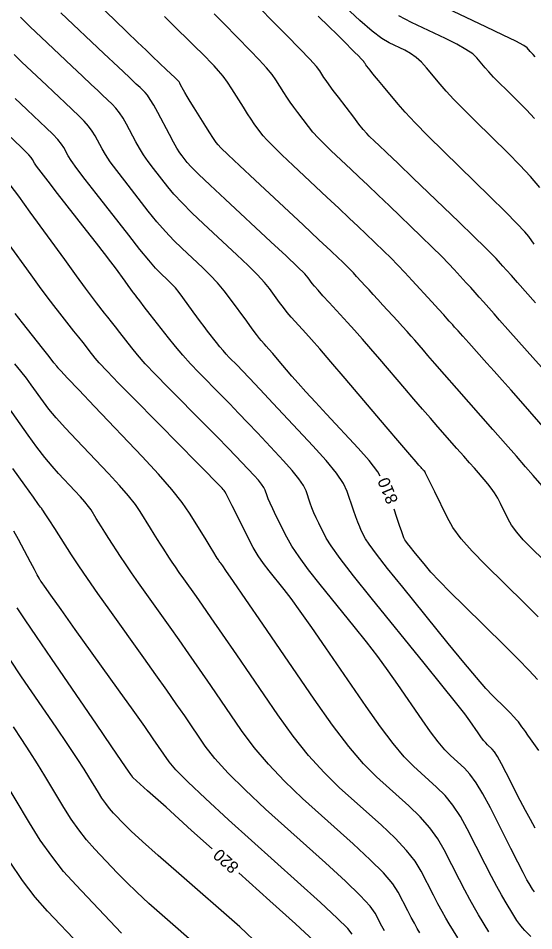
# Model space of a CAD drawing. Extents: x 2082232 to 2083549, y 592624 to 593832.
# Drawn here: x 2082349.4 to 2082379.6, y 593225.4 to 593278.8 of the extents above; entities that cross this region are included whole.
import ezdxf

# ---------------------------------------------------------------- set-up
doc = ezdxf.new("R2010")
doc.units = 0
doc.layers.add('DT_X_Contour_Major', color=7, linetype='Continuous')
doc.layers.add('DT_X_Contour_Minor', color=7, linetype='Continuous')

msp = doc.modelspace()

# ---------------------------------------------------------------- linework, layer by layer
at = {"layer": 'DT_X_Contour_Major'}
for points in [[(2082379.667, 593276.547), (2082379.545, 593276.672), (2082379.447, 593276.777), (2082379.372, 593276.863), (2082379.203, 593277.067), (2082379.004, 593277.202), (2082378.536, 593277.452), (2082377.798, 593277.817), (2082376.791, 593278.299), (2082373.744, 593279.736)], [(2082381.949, 593256.269), (2082379.537, 593258.954), (2082378.716, 593259.869), (2082378.063, 593260.599), (2082377.578, 593261.144), (2082377.26, 593261.504), (2082376.637, 593262.218), (2082376.399, 593262.488), (2082376.154, 593262.764), (2082375.901, 593263.046), (2082375.639, 593263.333), (2082374.932, 593264.106), (2082374.613, 593264.444), (2082374.185, 593264.877), (2082373.65, 593265.406), (2082373.006, 593266.03), (2082371.146, 593267.821), (2082370.481, 593268.459), (2082369.883, 593269.029), (2082369.353, 593269.533), (2082368.888, 593269.969), (2082367.739, 593271.043), (2082367.333, 593271.434), (2082366.975, 593271.802), (2082366.665, 593272.147), (2082366.404, 593272.469), (2082365.773, 593273.297), (2082365.545, 593273.603), (2082365.332, 593273.9), (2082365.136, 593274.188), (2082364.956, 593274.467), (2082364.496, 593275.199), (2082364.273, 593275.512), (2082363.949, 593275.903), (2082363.524, 593276.372), (2082362.999, 593276.919), (2082361.461, 593278.479), (2082360.894, 593279.052)], [(2082370.608, 593252.013), (2082370.455, 593252.266), (2082369.95, 593252.938), (2082369.316, 593253.658), (2082367.455, 593255.645), (2082366.805, 593256.343), (2082366.252, 593256.947), (2082365.794, 593257.456), (2082365.433, 593257.871), (2082364.597, 593258.851), (2082364.314, 593259.182), (2082364.092, 593259.441), (2082363.93, 593259.626), (2082363.829, 593259.739), (2082363.641, 593259.943), (2082363.535, 593260.071), (2082363.358, 593260.302), (2082363.11, 593260.636), (2082362.791, 593261.073), (2082361.845, 593262.374), (2082361.477, 593262.855), (2082361.082, 593263.321), (2082360.661, 593263.772), (2082360.214, 593264.208), (2082358.984, 593265.35), (2082358.516, 593265.808), (2082358.035, 593266.323), (2082357.539, 593266.895), (2082357.03, 593267.525), (2082355.654, 593269.282), (2082355.183, 593269.894), (2082354.805, 593270.411), (2082354.518, 593270.834), (2082354.323, 593271.163), (2082353.924, 593271.914), (2082353.753, 593272.198), (2082353.541, 593272.487), (2082353.286, 593272.78), (2082352.989, 593273.078), (2082352.141, 593273.878), (2082351.812, 593274.188), (2082351.461, 593274.519), (2082351.09, 593274.869), (2082349.62, 593276.257), (2082349.186, 593276.677)], [(2082376.964, 593225.355), (2082376.352, 593226.359), (2082376.11, 593226.77), (2082375.843, 593227.25), (2082375.551, 593227.798), (2082375.233, 593228.415), (2082374.351, 593230.151), (2082373.974, 593230.801), (2082373.502, 593231.446), (2082372.936, 593232.088), (2082372.277, 593232.725), (2082370.391, 593234.421), (2082369.632, 593235.183), (2082368.768, 593236.196), (2082367.8, 593237.46), (2082366.727, 593238.977), (2082363.727, 593243.355), (2082362.737, 593244.8), (2082362.017, 593245.85), (2082361.567, 593246.505), (2082361.387, 593246.766), (2082361.266, 593246.935), (2082361.223, 593246.995), (2082361.187, 593247.047), (2082361.156, 593247.093), (2082361.13, 593247.131), (2082361.07, 593247.225), (2082361.008, 593247.324), (2082360.868, 593247.551), (2082360.648, 593247.908), (2082360.349, 593248.392), (2082359.448, 593249.856), (2082359.022, 593250.474), (2082358.418, 593251.23), (2082357.637, 593252.125), (2082356.678, 593253.158), (2082353.885, 593256.098), (2082352.968, 593257.064), (2082352.313, 593257.755), (2082351.918, 593258.171), (2082351.784, 593258.314), (2082351.774, 593258.327), (2082351.77, 593258.332), (2082351.766, 593258.338), (2082351.761, 593258.343), (2082351.756, 593258.349), (2082351.741, 593258.366), (2082351.681, 593258.441), (2082351.512, 593258.654), (2082351.234, 593259.006), (2082350.847, 593259.495), (2082349.671, 593260.984), (2082349.249, 593261.522)], [(2082379.795, 593240.126), (2082379.318, 593240.654), (2082378.677, 593241.319), (2082377.872, 593242.12), (2082375.509, 593244.437), (2082374.702, 593245.235), (2082374.055, 593245.892), (2082373.569, 593246.409), (2082373.242, 593246.784), (2082372.583, 593247.596), (2082372.364, 593247.868), (2082372.201, 593248.076), (2082372.094, 593248.218), (2082372.044, 593248.296), (2082371.983, 593248.418), (2082371.94, 593248.526), (2082371.857, 593248.761), (2082371.734, 593249.121), (2082371.57, 593249.607), (2082371.411, 593250.081)], [(2082360.761, 593230.223), (2082359.568, 593231.297), (2082358.067, 593232.647), (2082356.993, 593233.614), (2082356.347, 593234.196), (2082356.128, 593234.396), (2082356.115, 593234.415), (2082356.108, 593234.425), (2082356.097, 593234.441), (2082356.082, 593234.462), (2082356.063, 593234.488), (2082356.008, 593234.566), (2082355.866, 593234.771), (2082355.484, 593235.33), (2082354.86, 593236.241), (2082353.995, 593237.505), (2082351.367, 593241.346), (2082350.488, 593242.635), (2082349.821, 593243.622), (2082349.366, 593244.307)], [(2082366.725, 593224.847), (2082365.644, 593225.828), (2082364.14, 593227.184), (2082362.323, 593228.819)]]:
    msp.add_lwpolyline(points, dxfattribs=at)
at = {"layer": 'DT_X_Contour_Minor'}
for points in [[(2082380.597, 593250.854), (2082379.553, 593252.06), (2082379.112, 593252.568), (2082378.571, 593253.186), (2082377.931, 593253.915), (2082377.191, 593254.755), (2082375.085, 593257.143), (2082374.37, 593257.955), (2082373.806, 593258.597), (2082373.392, 593259.072), (2082373.127, 593259.378), (2082372.623, 593259.97), (2082372.418, 593260.207), (2082372.181, 593260.475), (2082371.911, 593260.773), (2082371.61, 593261.102), (2082370.763, 593262.021), (2082370.461, 593262.35), (2082370.189, 593262.645), (2082369.948, 593262.907), (2082369.738, 593263.137), (2082369.219, 593263.704), (2082369.036, 593263.902), (2082368.878, 593264.071), (2082368.744, 593264.209), (2082368.634, 593264.318), (2082368.373, 593264.569), (2082368.157, 593264.774), (2082367.703, 593265.199), (2082367.012, 593265.846), (2082366.084, 593266.714), (2082363.291, 593269.323), (2082362.369, 593270.186), (2082361.698, 593270.818), (2082361.279, 593271.22), (2082361.111, 593271.392), (2082360.997, 593271.541), (2082360.928, 593271.641), (2082360.805, 593271.829), (2082360.629, 593272.105), (2082360.399, 593272.469), (2082359.717, 593273.556), (2082359.485, 593273.927), (2082359.303, 593274.224), (2082359.169, 593274.448), (2082359.085, 593274.598), (2082358.925, 593274.899), (2082358.871, 593274.999), (2082358.829, 593275.074), (2082358.799, 593275.123), (2082358.781, 593275.147), (2082358.749, 593275.178), (2082358.7, 593275.224), (2082358.576, 593275.341), (2082358.103, 593275.788), (2082357.274, 593276.571), (2082356.901, 593276.925), (2082356.406, 593277.4), (2082355.789, 593277.995), (2082355.049, 593278.712), (2082352.912, 593280.783)], [(2082379.678, 593262.146), (2082378.632, 593263.344), (2082378.276, 593263.751), (2082377.994, 593264.073), (2082377.785, 593264.309), (2082377.649, 593264.46), (2082377.386, 593264.748), (2082377.174, 593264.963), (2082376.738, 593265.391), (2082376.078, 593266.031), (2082375.192, 593266.885), (2082372.532, 593269.447), (2082371.643, 593270.301), (2082370.974, 593270.945), (2082370.523, 593271.376), (2082370.291, 593271.597), (2082369.964, 593271.902), (2082369.814, 593272.057), (2082369.613, 593272.293), (2082369.358, 593272.61), (2082369.051, 593273.007), (2082368.162, 593274.175), (2082367.858, 593274.576), (2082367.616, 593274.905), (2082367.433, 593275.16), (2082367.311, 593275.343), (2082367.067, 593275.732), (2082366.876, 593275.972), (2082366.488, 593276.399), (2082365.902, 593277.014), (2082365.118, 593277.816), (2082362.764, 593280.206)], [(2082379.932, 593268.9), (2082379.394, 593269.542), (2082378.78, 593270.212), (2082378.091, 593270.91), (2082376.151, 593272.807), (2082375.477, 593273.475), (2082374.912, 593274.053), (2082374.455, 593274.542), (2082374.106, 593274.943), (2082373.319, 593275.892), (2082373.018, 593276.224), (2082372.704, 593276.507), (2082372.378, 593276.742), (2082372.04, 593276.929), (2082371.121, 593277.363), (2082370.702, 593277.617), (2082370.134, 593278.053), (2082369.417, 593278.673), (2082368.551, 593279.476)], [(2082379.844, 593243.783), (2082379.047, 593244.585), (2082376.765, 593246.822), (2082375.982, 593247.626), (2082375.346, 593248.359), (2082374.856, 593249.023), (2082374.513, 593249.617), (2082373.793, 593251.107), (2082373.553, 593251.6), (2082373.376, 593251.959), (2082373.259, 593252.186), (2082373.205, 593252.28), (2082373.141, 593252.354), (2082373.114, 593252.385), (2082373.081, 593252.422), (2082373.042, 593252.467), (2082372.997, 593252.518), (2082372.868, 593252.664), (2082372.712, 593252.845), (2082372.342, 593253.278), (2082371.758, 593253.963), (2082370.959, 593254.9), (2082368.541, 593257.735), (2082367.719, 593258.698), (2082367.064, 593259.458), (2082366.576, 593260.017), (2082366.256, 593260.375), (2082365.626, 593261.058), (2082365.391, 593261.321), (2082365.161, 593261.596), (2082364.933, 593261.883), (2082364.709, 593262.182), (2082364.117, 593262.997), (2082363.832, 593263.349), (2082363.419, 593263.795), (2082362.878, 593264.335), (2082362.211, 593264.968), (2082360.26, 593266.781), (2082359.581, 593267.426), (2082359.006, 593268.001), (2082358.535, 593268.507), (2082358.169, 593268.943), (2082357.33, 593270.014), (2082357.03, 593270.412), (2082356.757, 593270.806), (2082356.513, 593271.195), (2082356.296, 593271.579), (2082355.757, 593272.597), (2082355.552, 593272.956), (2082355.345, 593273.271), (2082355.134, 593273.542), (2082354.92, 593273.768), (2082354.343, 593274.311), (2082354.07, 593274.569), (2082353.682, 593274.935), (2082353.18, 593275.409), (2082352.563, 593275.992), (2082350.765, 593277.689), (2082350.124, 593278.3), (2082349.549, 593278.861)], [(2082380.833, 593246.451), (2082379.448, 593247.808), (2082378.973, 593248.296), (2082378.587, 593248.742), (2082378.29, 593249.144), (2082378.081, 593249.505), (2082377.644, 593250.409), (2082377.475, 593250.736), (2082377.294, 593251.038), (2082377.103, 593251.315), (2082376.901, 593251.567), (2082376.347, 593252.207), (2082376.113, 593252.476), (2082375.826, 593252.804), (2082375.486, 593253.191), (2082375.094, 593253.637), (2082373.976, 593254.904), (2082373.541, 593255.4), (2082373.074, 593255.938), (2082372.575, 593256.517), (2082372.043, 593257.139), (2082370.582, 593258.852), (2082370.053, 593259.469), (2082369.56, 593260.034), (2082369.103, 593260.548), (2082368.683, 593261.01), (2082367.611, 593262.173), (2082367.248, 593262.57), (2082366.963, 593262.889), (2082366.757, 593263.129), (2082366.628, 593263.292), (2082366.39, 593263.62), (2082366.186, 593263.844), (2082365.755, 593264.27), (2082365.095, 593264.898), (2082364.208, 593265.728), (2082361.537, 593268.211), (2082360.646, 593269.044), (2082359.978, 593269.68), (2082359.532, 593270.119), (2082359.308, 593270.361), (2082359.007, 593270.745), (2082358.876, 593270.931), (2082358.71, 593271.202), (2082358.508, 593271.557), (2082358.27, 593271.996), (2082357.589, 593273.28), (2082357.352, 593273.714), (2082357.149, 593274.055), (2082356.982, 593274.303), (2082356.85, 593274.458), (2082356.546, 593274.744), (2082356.328, 593274.95), (2082355.903, 593275.352), (2082355.27, 593275.949), (2082354.429, 593276.743), (2082351.91, 593279.122)], [(2082380.416, 593254.595), (2082378.826, 593256.398), (2082378.254, 593257.045), (2082377.733, 593257.633), (2082377.262, 593258.162), (2082376.841, 593258.632), (2082375.784, 593259.808), (2082375.428, 593260.205), (2082375.153, 593260.513), (2082374.957, 593260.732), (2082374.842, 593260.862), (2082374.642, 593261.091), (2082374.523, 593261.225), (2082374.314, 593261.456), (2082374.016, 593261.783), (2082373.629, 593262.207), (2082372.479, 593263.465), (2082372.051, 593263.925), (2082371.632, 593264.364), (2082371.222, 593264.78), (2082370.82, 593265.174), (2082369.759, 593266.195), (2082369.319, 593266.616), (2082368.793, 593267.114), (2082368.182, 593267.69), (2082367.486, 593268.342), (2082365.515, 593270.183), (2082364.851, 593270.81), (2082364.337, 593271.31), (2082363.972, 593271.684), (2082363.758, 593271.93), (2082363.385, 593272.419), (2082363.231, 593272.63), (2082363.049, 593272.896), (2082362.839, 593273.216), (2082362.6, 593273.592), (2082361.925, 593274.666), (2082361.67, 593275.053), (2082361.411, 593275.408), (2082361.147, 593275.73), (2082360.879, 593276.021), (2082360.158, 593276.753), (2082359.819, 593277.092), (2082359.341, 593277.563), (2082358.725, 593278.165), (2082357.971, 593278.897)], [(2082379.618, 593265.577), (2082379.292, 593266.039), (2082379.058, 593266.315), (2082378.602, 593266.795), (2082377.923, 593267.479), (2082377.021, 593268.367), (2082374.32, 593271.009), (2082373.394, 593271.925), (2082372.64, 593272.69), (2082372.059, 593273.304), (2082371.65, 593273.768), (2082370.791, 593274.805), (2082370.501, 593275.156), (2082370.274, 593275.433), (2082370.11, 593275.635), (2082370.01, 593275.762), (2082369.826, 593276.003), (2082369.765, 593276.084), (2082369.718, 593276.147), (2082369.685, 593276.192), (2082369.667, 593276.218), (2082369.638, 593276.265), (2082369.596, 593276.313), (2082369.492, 593276.423), (2082369.326, 593276.594), (2082369.098, 593276.826), (2082368.407, 593277.527), (2082368.074, 593277.858), (2082367.593, 593278.326), (2082366.965, 593278.93)], [(2082379.638, 593272.946), (2082379.16, 593273.453), (2082377.981, 593274.606), (2082377.572, 593275.011), (2082377.229, 593275.362), (2082376.951, 593275.659), (2082376.739, 593275.903), (2082376.261, 593276.48), (2082376.011, 593276.713), (2082375.62, 593276.979), (2082375.088, 593277.28), (2082374.415, 593277.614), (2082372.433, 593278.549), (2082371.691, 593278.942)], [(2082379.879, 593235.978), (2082379.4, 593236.644), (2082379.233, 593236.876), (2082379.093, 593237.072), (2082378.977, 593237.233), (2082378.888, 593237.358), (2082378.685, 593237.643), (2082378.582, 593237.772), (2082378.424, 593237.946), (2082378.213, 593238.165), (2082377.947, 593238.43), (2082377.168, 593239.194), (2082376.787, 593239.599), (2082376.23, 593240.24), (2082375.496, 593241.117), (2082374.585, 593242.23), (2082371.922, 593245.515), (2082371.036, 593246.615), (2082370.378, 593247.454), (2082369.946, 593248.031), (2082369.741, 593248.347), (2082369.496, 593248.838), (2082369.399, 593249.05), (2082369.29, 593249.319), (2082369.17, 593249.644), (2082369.039, 593250.024), (2082368.674, 593251.115), (2082368.445, 593251.588), (2082368.034, 593252.192), (2082367.439, 593252.925), (2082366.662, 593253.788), (2082364.345, 593256.262), (2082363.562, 593257.096), (2082362.952, 593257.744), (2082362.514, 593258.206), (2082362.248, 593258.48), (2082361.77, 593258.964), (2082361.588, 593259.154), (2082361.403, 593259.362), (2082361.214, 593259.588), (2082361.02, 593259.832), (2082360.5, 593260.507), (2082360.301, 593260.767), (2082360.094, 593261.042), (2082359.879, 593261.332), (2082359.656, 593261.637), (2082359.051, 593262.469), (2082358.829, 593262.764), (2082358.616, 593263.026), (2082358.412, 593263.253), (2082358.217, 593263.448), (2082357.708, 593263.92), (2082357.451, 593264.19), (2082357.063, 593264.644), (2082356.543, 593265.283), (2082355.891, 593266.107), (2082353.977, 593268.55), (2082353.337, 593269.375), (2082352.852, 593270.016), (2082352.523, 593270.473), (2082352.349, 593270.746), (2082352.091, 593271.231), (2082351.954, 593271.44), (2082351.737, 593271.702), (2082351.438, 593272.018), (2082351.058, 593272.388), (2082349.938, 593273.445), (2082349.553, 593273.807), (2082349.241, 593274.102)], [(2082379.67, 593231.437), (2082379.387, 593231.93), (2082379.094, 593232.468), (2082378.793, 593233.049), (2082377.976, 593234.659), (2082377.695, 593235.199), (2082377.465, 593235.61), (2082377.286, 593235.894), (2082377.158, 593236.05), (2082376.885, 593236.296), (2082376.774, 593236.409), (2082376.642, 593236.564), (2082376.492, 593236.762), (2082376.323, 593237.002), (2082375.845, 593237.699), (2082375.544, 593238.106), (2082374.997, 593238.806), (2082374.206, 593239.797), (2082373.169, 593241.08), (2082370.078, 593244.892), (2082369.044, 593246.183), (2082368.259, 593247.198), (2082367.724, 593247.935), (2082367.438, 593248.397), (2082367.009, 593249.258), (2082366.857, 593249.575), (2082366.723, 593249.877), (2082366.607, 593250.167), (2082366.508, 593250.442), (2082366.268, 593251.159), (2082366.117, 593251.47), (2082365.847, 593251.867), (2082365.456, 593252.349), (2082364.945, 593252.917), (2082363.421, 593254.544), (2082362.86, 593255.14), (2082362.318, 593255.707), (2082361.796, 593256.247), (2082361.294, 593256.758), (2082359.983, 593258.084), (2082359.503, 593258.584), (2082359.047, 593259.087), (2082358.615, 593259.594), (2082358.207, 593260.106), (2082357.15, 593261.474), (2082356.799, 593261.93), (2082356.536, 593262.27), (2082356.362, 593262.494), (2082356.278, 593262.602), (2082356.171, 593262.737), (2082356.11, 593262.818), (2082356.005, 593262.959), (2082355.858, 593263.16), (2082355.668, 593263.421), (2082355.105, 593264.197), (2082354.84, 593264.553), (2082354.471, 593265.038), (2082353.996, 593265.652), (2082353.416, 593266.395), (2082351.728, 593268.55), (2082351.168, 593269.267), (2082350.756, 593269.803), (2082350.492, 593270.157), (2082350.375, 593270.33), (2082350.259, 593270.548), (2082350.184, 593270.654), (2082350.048, 593270.809), (2082349.85, 593271.011), (2082349.59, 593271.261), (2082348.815, 593271.992)], [(2082379.635, 593227.695), (2082379.519, 593227.853), (2082379.313, 593228.192), (2082379.188, 593228.415), (2082378.97, 593228.829), (2082378.658, 593229.435), (2082378.252, 593230.231), (2082377.045, 593232.611), (2082376.61, 593233.426), (2082376.213, 593234.086), (2082375.854, 593234.591), (2082375.531, 593234.942), (2082374.721, 593235.671), (2082374.388, 593236.007), (2082373.999, 593236.469), (2082373.553, 593237.056), (2082373.05, 593237.769), (2082371.632, 593239.838), (2082371.073, 593240.632), (2082370.461, 593241.462), (2082369.796, 593242.328), (2082369.077, 593243.23), (2082367.087, 593245.684), (2082366.406, 593246.546), (2082365.853, 593247.294), (2082365.43, 593247.928), (2082365.135, 593248.447), (2082364.522, 593249.679), (2082364.316, 593250.099), (2082364.156, 593250.436), (2082364.043, 593250.689), (2082363.977, 593250.86), (2082363.861, 593251.203), (2082363.789, 593251.353), (2082363.66, 593251.543), (2082363.473, 593251.774), (2082363.228, 593252.046), (2082362.497, 593252.825), (2082362.157, 593253.183), (2082361.684, 593253.67), (2082361.079, 593254.288), (2082360.341, 593255.036), (2082358.196, 593257.205), (2082357.459, 593257.959), (2082356.857, 593258.596), (2082356.391, 593259.114), (2082356.06, 593259.514), (2082355.357, 593260.425), (2082355.105, 593260.751), (2082354.874, 593261.048), (2082354.665, 593261.316), (2082354.478, 593261.553), (2082354.009, 593262.147), (2082353.76, 593262.473), (2082353.366, 593263.004), (2082352.825, 593263.74), (2082352.14, 593264.682), (2082350.117, 593267.467), (2082349.447, 593268.389), (2082348.956, 593269.063)], [(2082379.413, 593225.094), (2082379.059, 593225.439), (2082378.919, 593225.592), (2082378.765, 593225.79), (2082378.596, 593226.034), (2082378.413, 593226.323), (2082377.906, 593227.155), (2082377.691, 593227.525), (2082377.425, 593228.009), (2082377.109, 593228.609), (2082376.742, 593229.323), (2082375.698, 593231.381), (2082375.292, 593232.113), (2082374.858, 593232.766), (2082374.395, 593233.339), (2082373.904, 593233.834), (2082372.556, 593235.046), (2082372.003, 593235.605), (2082371.356, 593236.373), (2082370.614, 593237.35), (2082369.777, 593238.536), (2082367.419, 593241.978), (2082366.603, 593243.159), (2082365.926, 593244.119), (2082365.386, 593244.86), (2082364.984, 593245.38), (2082364.096, 593246.475), (2082363.772, 593246.901), (2082363.463, 593247.359), (2082363.172, 593247.848), (2082362.897, 593248.369), (2082362.185, 593249.799), (2082361.947, 593250.275), (2082361.768, 593250.63), (2082361.648, 593250.864), (2082361.586, 593250.977), (2082361.5, 593251.117), (2082361.461, 593251.174), (2082361.412, 593251.238), (2082361.35, 593251.31), (2082361.277, 593251.389), (2082361.067, 593251.61), (2082360.872, 593251.81), (2082360.444, 593252.245), (2082359.783, 593252.914), (2082358.889, 593253.818), (2082356.195, 593256.542), (2082355.295, 593257.456), (2082354.615, 593258.158), (2082354.154, 593258.647), (2082353.913, 593258.923), (2082353.564, 593259.375), (2082353.411, 593259.573), (2082353.212, 593259.827), (2082352.968, 593260.137), (2082352.679, 593260.504), (2082351.847, 593261.557), (2082351.508, 593261.993), (2082351.117, 593262.509), (2082350.674, 593263.107), (2082350.177, 593263.787), (2082348.783, 593265.706)], [(2082375.134, 593225.014), (2082374.635, 593225.832), (2082374.438, 593226.167), (2082374.22, 593226.558), (2082373.982, 593227.004), (2082373.723, 593227.507), (2082373.005, 593228.922), (2082372.656, 593229.488), (2082372.147, 593230.126), (2082371.478, 593230.836), (2082370.649, 593231.617), (2082368.227, 593233.796), (2082367.319, 593234.675), (2082366.413, 593235.679), (2082365.51, 593236.808), (2082364.608, 593238.06), (2082362.205, 593241.567), (2082361.382, 593242.767), (2082360.714, 593243.735), (2082360.202, 593244.471), (2082359.845, 593244.977), (2082359.102, 593246.016), (2082358.841, 593246.384), (2082358.615, 593246.708), (2082358.424, 593246.989), (2082358.268, 593247.226), (2082357.898, 593247.799), (2082357.749, 593248.034), (2082357.577, 593248.306), (2082357.384, 593248.617), (2082357.168, 593248.966), (2082356.564, 593249.948), (2082356.278, 593250.362), (2082355.873, 593250.87), (2082355.348, 593251.47), (2082354.705, 593252.163), (2082352.832, 593254.135), (2082352.184, 593254.829), (2082351.645, 593255.432), (2082351.215, 593255.944), (2082350.894, 593256.365), (2082350.182, 593257.365), (2082349.897, 593257.751), (2082349.574, 593258.159), (2082349.215, 593258.588)], [(2082372.918, 593225.305), (2082372.766, 593225.563), (2082372.598, 593225.865), (2082372.413, 593226.21), (2082372.213, 593226.599), (2082371.658, 593227.692), (2082371.338, 593228.176), (2082370.791, 593228.806), (2082370.019, 593229.584), (2082369.022, 593230.509), (2082366.062, 593233.171), (2082365.006, 593234.168), (2082364.058, 593235.163), (2082363.219, 593236.155), (2082362.488, 593237.144), (2082360.682, 593239.779), (2082360.026, 593240.733), (2082359.411, 593241.619), (2082358.837, 593242.438), (2082358.304, 593243.188), (2082356.938, 593245.097), (2082356.458, 593245.773), (2082356.043, 593246.369), (2082355.692, 593246.884), (2082355.405, 593247.32), (2082354.727, 593248.374), (2082354.49, 593248.743), (2082354.287, 593249.061), (2082354.12, 593249.326), (2082353.987, 593249.54), (2082353.679, 593250.04), (2082353.533, 593250.251), (2082353.327, 593250.509), (2082353.06, 593250.815), (2082352.733, 593251.168), (2082351.779, 593252.172), (2082351.4, 593252.595), (2082350.977, 593253.11), (2082350.512, 593253.717), (2082350.004, 593254.416), (2082348.591, 593256.403)], [(2082370.845, 593225.417), (2082370.703, 593225.691), (2082370.312, 593226.462), (2082370.019, 593226.863), (2082369.436, 593227.486), (2082368.561, 593228.332), (2082367.395, 593229.401), (2082363.897, 593232.546), (2082362.693, 593233.661), (2082361.703, 593234.646), (2082360.928, 593235.502), (2082360.368, 593236.228), (2082359.16, 593237.991), (2082358.67, 593238.7), (2082358.108, 593239.504), (2082357.472, 593240.404), (2082356.763, 593241.398), (2082354.774, 593244.178), (2082354.076, 593245.162), (2082353.471, 593246.029), (2082352.96, 593246.78), (2082352.542, 593247.414), (2082351.555, 593248.949), (2082351.23, 593249.453), (2082350.997, 593249.815), (2082350.856, 593250.036), (2082350.806, 593250.113), (2082350.794, 593250.132), (2082350.789, 593250.139), (2082350.782, 593250.149), (2082350.772, 593250.16), (2082350.76, 593250.172), (2082350.726, 593250.209), (2082350.615, 593250.36), (2082350.31, 593250.787), (2082349.809, 593251.489), (2082349.114, 593252.467)], [(2082368.965, 593225.233), (2082368.701, 593225.551), (2082368.08, 593226.166), (2082367.102, 593227.08), (2082365.768, 593228.292), (2082361.733, 593231.921), (2082360.38, 593233.154), (2082359.348, 593234.13), (2082358.638, 593234.849), (2082358.248, 593235.312), (2082357.637, 593236.203), (2082357.319, 593236.661), (2082356.82, 593237.367), (2082356.142, 593238.32), (2082355.285, 593239.52), (2082352.759, 593243.052), (2082351.927, 593244.215), (2082351.325, 593245.057), (2082350.953, 593245.578), (2082350.812, 593245.777), (2082350.741, 593245.88), (2082350.718, 593245.914), (2082350.7, 593245.94), (2082350.688, 593245.959), (2082350.682, 593245.969), (2082350.672, 593245.985), (2082350.636, 593246.052), (2082350.536, 593246.241), (2082350.371, 593246.553), (2082350.142, 593246.986), (2082349.444, 593248.303), (2082349.167, 593248.808)], [(2082363.584, 593224.529), (2082362.381, 593225.651), (2082358.814, 593228.772), (2082357.613, 593229.828), (2082356.686, 593230.656), (2082356.032, 593231.255), (2082355.652, 593231.626), (2082355.004, 593232.31), (2082354.766, 593232.577), (2082354.537, 593232.867), (2082354.317, 593233.178), (2082354.108, 593233.512), (2082353.56, 593234.431), (2082353.286, 593234.871), (2082352.874, 593235.502), (2082352.324, 593236.322), (2082351.636, 593237.334), (2082349.617, 593240.284), (2082348.921, 593241.309)], [(2082360.037, 593224.416), (2082357.843, 593226.336), (2082357.061, 593227.03), (2082356.363, 593227.675), (2082355.747, 593228.269), (2082355.214, 593228.813), (2082353.903, 593230.197), (2082353.42, 593230.738), (2082352.958, 593231.324), (2082352.514, 593231.954), (2082352.089, 593232.629), (2082350.982, 593234.489), (2082350.556, 593235.191), (2082350.109, 593235.901), (2082349.64, 593236.62), (2082349.15, 593237.349)], [(2082355.462, 593225.283), (2082354.775, 593226.001), (2082352.801, 593228.084), (2082352.075, 593228.899), (2082351.378, 593229.781), (2082350.71, 593230.73), (2082350.071, 593231.747), (2082348.404, 593234.546)], [(2082353.018, 593224.58), (2082351.134, 593226.568), (2082350.416, 593227.389), (2082349.672, 593228.362), (2082348.904, 593229.488)]]:
    msp.add_lwpolyline(points, dxfattribs=at)

# ---------------------------------------------------------------- texts
at = {"layer": 'DT_X_Contour_Major'}
for s, rotation, p in [('810', 112.5692, (2082371.665, 593250.575)), ('820', 138.0314, (2082362.387, 593229.232))]:
    msp.add_text(s, height=0.7, rotation=rotation, dxfattribs=at).set_placement(p)

doc.saveas('drawing.dxf')
